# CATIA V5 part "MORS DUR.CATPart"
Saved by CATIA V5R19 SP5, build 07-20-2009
Part number: MORS
Bounding box of the stored display mesh (mm): x 0 to 80, y -18 to 18, z 0 to 45
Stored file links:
  C:\Documents and Settings\gilbert\Mes documents\Mon travail\travail 2011\IPM1\TP INDUS\SEANCE 13\MORS +MANDRIN TBI\MORS DUR.CATPart
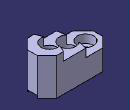
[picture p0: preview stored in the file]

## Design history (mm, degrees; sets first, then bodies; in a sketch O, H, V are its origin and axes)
Body1 (main body)
  Sketch1 on xy-plane, origin (0, 0, 0), H (1, 0, 0), V (0, 1, 0)
    line L1 (80, -18) -> (80, 18)
    line L2 (80, 18) -> (0, 18)
    line L3 (0, 18) -> (0, -18)
    line L4 (0, -18) -> (80, -18)
    distance L2 H = 18
    horizontal: L2 H, L4 H
    vertical: L1 V, L3 V
  Pad1: profile Sketch1, direction (0, 0, 1), length 45
  Chamfer1: length 12, angle 45, on edge [face of Pad1 from Sketch1.L1 | face of Pad1 from Sketch1.L4]; edge [face of Pad1 from Sketch1.L2 | face of Pad1 from Sketch1.L1]; edge [face of Pad1 from Sketch1.L4 | face of Pad1 from Sketch1.L3]; edge [face of Pad1 from Sketch1.L3 | face of Pad1 from Sketch1.L2]
  Sketch2 on end face of Pad1, origin (0, 0, 45), H (1, 0, 0), V (0, 1, 0)
    circle A1 centre (90, 0) radius 60
    point P1 (90, 0)
    circle A2 centre (90, 0) radius 100.0798
    distance P1 V = 90
    radius A1 = 60
    coincidence: P1 H
  Pocket1: profile Sketch2, direction (0, 0, -1), length 20
  Sketch3 on end face of Pad1, origin (0, 0, 45), H (1, 0, 0), V (0, 1, 0)
    circle A1 centre (90, 0) radius 35
    point P1 (90, 0)
    circle A2 centre (90, 0) radius 67.1404
    radius A1 = 35
    distance P1 V = 90
    coincidence: P1 H
  Pocket2: profile Sketch3, direction (0, 0, -1), length 10
  Sketch4 on end face of Pad1, origin (59, 0, 45), H (1, 0, 0), V (0, 1, 0)
    point P1 (0, 0)
    reference projected point E1 (0, 0) from Sketch8.P1
    coincidence: E1 P1
  Hole1: placed by Sketch4, at (59, 0, 45) direction (0, 0, -1), diameter 10, through (limit type 3), counterbore diameter 20, counterbore depth 30
  Sketch5 on end face of Pad1, origin (37, 0, 45), H (1, 0, 0), V (0, 1, 0)
    point P1 (0, 0)
    reference projected point E1 (0, 0) from Sketch8.P2
    coincidence: E1 P1
  Hole2: placed by Sketch5, at (37, 0, 45) direction (0, 0, -1), diameter 10, through (limit type 3), counterbore diameter 20, counterbore depth 30
  Sketch6 on end face of Pad1, origin (15, 0, 45), H (1, 0, 0), V (0, 1, 0)
    point P1 (0, 0)
    reference projected point E1 (0, 0) from Sketch8.P3
    coincidence: E1 P1
  Hole3: placed by Sketch6, at (15, 0, 45) direction (0, 0, -1), diameter 10, through (limit type 3), counterbore diameter 20, counterbore depth 30
  Sketch7 on start face of Pad1, origin (0, 0, 0), H (1, 0, 0), V (0, -1, 0)
    line L1 (-10.0018, 6.5) -> (90.782, 6.5)
    line L2 (90.782, 6.5) -> (90.782, -6.5)
    line L3 (90.782, -6.5) -> (-10.0018, -6.5)
    line L4 (-10.0018, -6.5) -> (-10.0018, 6.5)
    distance L1 H = 6.5
    length L4 = 13
    horizontal: L1 H, L3 H
    vertical: L2 V, L4 V
  Pocket3: profile Sketch7, direction (0, 0, 1), length 3
  Sketch8 on end face of Pad1, origin (0, 0, 45), H (1, 0, 0), V (0, 1, 0)
    point P1 (59, 0)
    point P2 (37, 0)
    point P3 (15, 0)
    distance P1 P2 = 22
    distance P2 P3 = 22
    distance P3 V = 15
    coincidence: P1 H, P2 H, P3 H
